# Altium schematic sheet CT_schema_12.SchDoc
size 147 x 119 mm
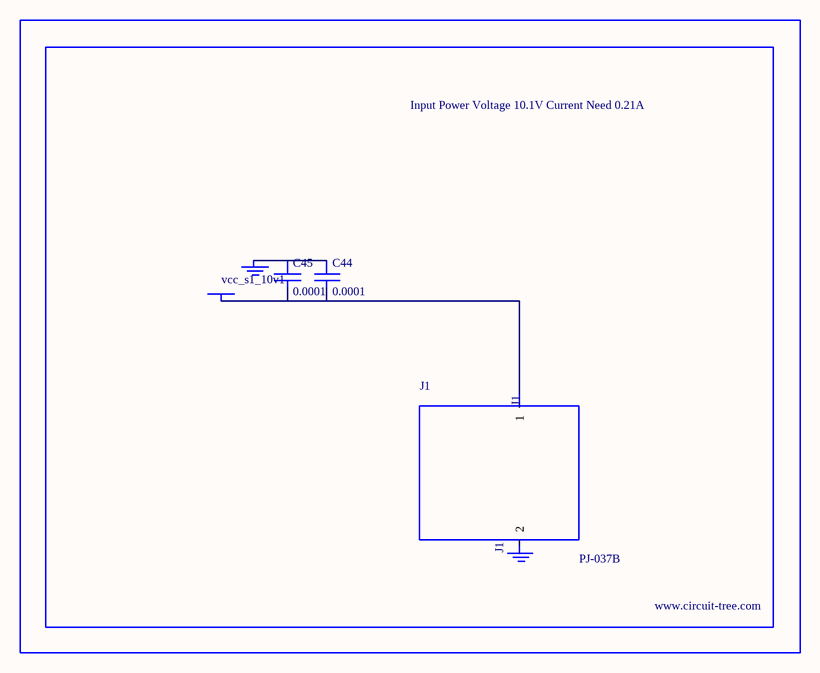
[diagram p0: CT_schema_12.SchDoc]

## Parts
BORDER11  (no value)
C44  0.0001  [EXV-9H]
C45  0.0001  [EXV-9H]
GND_INSTANCE_11_0  (no value)
GND_INSTANCE_11_1  (no value)
J1  PJ-037B  [PJ-037B_PACKAGE]
POWER_INSTANCE_11_0  vcc_s1_10v1

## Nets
NetC44_1: C44.1 C45.1 GND_INSTANCE_11_0.0(GND)
NetC44_2: C44.2 C45.2 J1.1 POWER_INSTANCE_11_0.0(PWR)

Not connected (* = marked no-connect by the designer): GND_INSTANCE_11_1 0(GND); J1 2

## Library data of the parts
BORDER11 = BORDER_PAGE11
C44 C45 = EDK107M035A9HAA
GND_INSTANCE_11_0 GND_INSTANCE_11_1 = GND
POWER_INSTANCE_11_0 = PWR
